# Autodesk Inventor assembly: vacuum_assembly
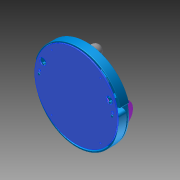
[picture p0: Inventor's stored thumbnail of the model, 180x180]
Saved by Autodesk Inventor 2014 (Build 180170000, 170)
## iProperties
Created: 2015-06
Part Number: vacuum_assembly
Document SubType Name: Assembly
Designer: common
Author: common
Author: s41632
Title: D:\rOy\FabLab\01 FABLAB Academy\18 Walter\vacuum_assembly.stp
Creation Date: 2015-06-12
Sending System: Autodesk Inventor 2014
Preprocessor: ST-DEVELOPER v15.2
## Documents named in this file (8)
- C:\Users\common\Documents\Inventor\Computer Design\Imported Components\vacuum_assembly\vacuum_assembly.iam
- C:\Users\common\Documents\Inventor\Computer Design\Imported Components\vacuum_assembly\Base.ipt
- C:\Users\common\Documents\Inventor\Computer Design\Imported Components\vacuum_assembly\fan.ipt
- C:\Users\common\Documents\Inventor\Computer Design\Imported Components\vacuum_assembly\motor_wheel.ipt
- C:\Users\common\Documents\Inventor\Computer Design\Imported Components\vacuum_assembly\roller.ipt
- C:\Users\common\Documents\Inventor\Computer Design\Imported Components\vacuum_assembly\Topplate.ipt
- C:\Users\common\Documents\Inventor\Computer Design\Imported Components\vacuum_assembly\SensorrearBumber.ipt
- C:\Users\common\Documents\Inventor\Computer Design\Imported Components\vacuum_assembly\SensorBumber.ipt
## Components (8 placed, 7 different names)
1. Base:1
2. fan:1
3. motor_wheel:1
4. motor_wheel:2
5. roller:1
6. Topplate:1
7. SensorrearBumber:1
8. SensorBumber:1
